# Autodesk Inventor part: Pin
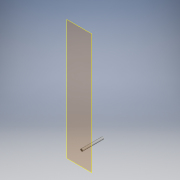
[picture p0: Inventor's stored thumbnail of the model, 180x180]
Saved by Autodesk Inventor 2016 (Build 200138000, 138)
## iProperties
Created: 2016-03
Part Number: Pin
Material: Generic
Document SubType Name: Modeling
Designer: fisher
Density: 1 g/cm^3
Appearance: Default
Author: fisher
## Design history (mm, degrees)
workplane "Work Plane1"
sketch "Sketch1"
  geometry: C1 r 2.526 at (0, -95.427); 1 further point
  constraints: 1 centre point
extrude "Extrusion1" new body sketch "Sketch1" distance "d0" = 44.45; taper "d1" = 0 deg
body "Solid1"
